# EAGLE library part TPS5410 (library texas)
1-A, WIDE INPUT RANGE, STEP-DOWN SWIFT? CONVERTER Source: U7 Texas TPS5410 Step Down Converter.pdf
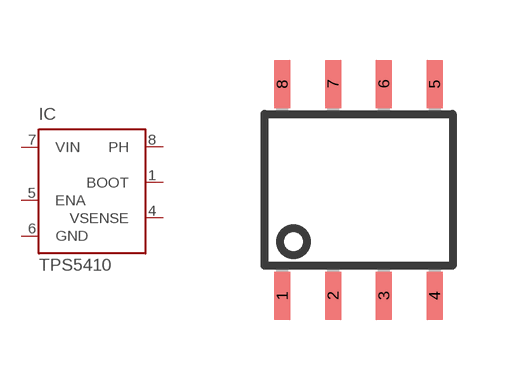
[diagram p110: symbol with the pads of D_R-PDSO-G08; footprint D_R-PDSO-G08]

Designator prefix IC

## TPS5410 (MPN: TPS5410DR; OC_FARNELL: 1329596; OC_NEWARK: 18M3223)  [D_R-PDSO-G08]
1  BOOT  out
4  VSENSE  in
5  ENA  in
6  GND  pwr
7  VIN  in
8  PH  out

## Footprint D_R-PDSO-G08 (pad centres in mm)
PLASTIC SMALL-OUTLINE PACKAGE SO 14 JEDEC MS-012, D Type Source: www.ti.com/.. slvs087l.pdf
smd 0.4 x 1.2: 1 -1.905,-2.65; 2 -0.635,-2.65; 3 0.635,-2.65; 4 1.905,-2.65; 5 1.905,2.65; 6 0.635,2.65; 7 -0.635,2.65; 8 -1.905,2.65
